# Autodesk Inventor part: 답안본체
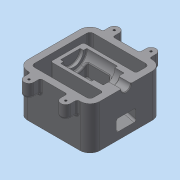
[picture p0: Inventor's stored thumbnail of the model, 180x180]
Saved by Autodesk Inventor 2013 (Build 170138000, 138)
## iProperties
Created: 2018-01
Part Number: 답안본체
Material: 일반
Document SubType Name: Modeling
Designer: dgall
Density: 1 g/cm^3
Author: dgall
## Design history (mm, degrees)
sketch "스케치1"
  geometry: L1 (-55, 55)-(55, 55); L2 (55, 55)-(55, -55); L3 (55, -55)-(-55, -55); L4 (-55, -55)-(-55, 55); 3 further points
  constraints: 8 end point, 2 midpoint, 2 perpendicular, 1 horizontal, 1 horizontal alignment, 1 parallel, 1 vertical alignment
  dimensions: "d0" = 110 distance of L1.start L1.end; "d2" = 110 distance of L1.end L2.end
extrude "돌출1" new body sketch "스케치1" distance "d3" = 65; taper "d4" = 0 deg
fillet "모깎기1" dims "d5" = 15
sketch "스케치2"
  geometry: L1 (55, 65)-(55, 0) reference; L2 (55, 0)-(-55, 0) reference; L3 (-55, 0)-(-55, 65) reference; L4 (-55, 65)-(55, 65) reference; 1 further point
  node "절단 모서리 투영1"
sketch "스케치3"
  geometry: L1 (55, 65)-(55, 0) reference; L2 (55, 0)-(-55, 0) reference; L3 (-55, 0)-(-55, 65) reference; L4 (-55, 65)-(55, 65) reference; L5 (-55, 65)-(55, 65); L6 (-55, 65)-(-55, 57.5); L7 (-55, 57.5)-(-36, 57.5); L8 (-36, 57.5)-(-36, 49); L9 (-36, 49)-(-22, 49); L10 (-22, 49)-(-22, 45); L11 (-22, 45)-(25, 45); L12 (25, 45)-(25, 50); L13 (25, 50)-(30, 50); L14 (30, 50)-(30, 65); 1 further point
  constraints: 20 end point, 5 parallel, 3 perpendicular, 2 point on line, 1 collinear
  dimensions: "d7" = 19 distance of L6.end L7.end; "d9" = 15 diameter of L7 L4; "d10" = 32 diameter of L9 L4; "d11" = 40 diameter of L11 L4; "d13" = 30 diameter of L13 L4; "d14" = 14 distance of L8.end L9.end; "d15" = 47 distance of L10.end L11.end; "d16" = 5 distance of L12.end L13.end
revolve "회전1" sketch "스케치3" stored, may be unused: angle "d17" = 90 deg
sketch "스케치4"
  geometry: L1 (55, 65)-(55, 0) reference; L2 (55, 0)-(-55, 0) reference; L3 (-55, 0)-(-55, 57.5) reference; L4 (-55, 57.5)-(-36, 57.5) reference; L5 (-36, 57.5)-(-36, 49) reference; L6 (-36, 49)-(-22, 49) reference; L7 (-22, 49)-(-22, 45) reference; L8 (-22, 45)-(25, 45) reference; L9 (25, 45)-(25, 50) reference; L10 (25, 50)-(30, 50) reference; L11 (30, 50)-(30, 65) reference; L12 (30, 65)-(55, 65) reference; L13 (-55, 29.061)-(-17, 39.243); L14 (-17, 39.243)-(-17, 45); L15 (-55, 11.061)-(20, 31.157); L16 (20, 31.157)-(20, 45); L17 (-45, 0)-(-45, 8.564); L18 (-45, 8.564)-(35, 30); L19 (35, 30)-(35, 65); L20 (45, 65)-(45, 0); L21 (-17, 45)-(-17, 65); L22 (20, 45)-(20, 65); L23 (20, 65)-(17.646, 65); L24 (17.646, 65)-(-17, 65); 1 further point
  constraints: 24 end point, 8 point on line, 6 parallel, 4 perpendicular, 3 vertical alignment, 1 horizontal alignment
  dimensions: "d19" = 18 distance of L15.start L13.start; "d21" = 37 horizontal distance of L16.end L13.end; "d22" = 75 deg angle of L13 L3; "d23" = 5 distance of L7.end L14.end; "d25" = 30 distance from line of L2 L18.end; "d26" = 10 distance between parallel lines of L20 L19; "d27" = 20 distance between parallel lines of L1 L19; "d28" = 5 distance between parallel lines of L15 L18; "d29" = 10 distance between parallel lines of L3 L17; "d32" = 20 distance of L14.end L21.end; "d34" = 20 distance of L16.end L22.end
  node "절단 모서리 투영3"
extrude "돌출2" cut sketch "스케치4" stored distance "d30" = 90; taper "d31" = 0 deg
extrude "돌출3" join sketch "스케치4" stored distance "d35" = 30; taper "d36" = 0 deg
sketch "스케치5"
  geometry: L1 (-35, 45)-(-35, -45) reference; L2 (55, 7.5)-(55, 40) reference; L3 (40, 55)-(-40, 55) reference; L4 (-40, -55)-(40, -55) reference; L5 (55, -40)-(55, -7.5) reference; L6 (36, 16)-(36, 7.5) reference; L7 (-35, -45)-(45, -45); L8 (45, -45)-(45, -25); L9 (45, -25)-(-35, -25); L10 (-35, 25)-(45, 25); L11 (45, 25)-(45, 45); L12 (45, 45)-(-35, 45); 1 further point
  constraints: 12 end point, 5 perpendicular, 2 point on line, 1 parallel
  dimensions: "d37" = 30 distance between parallel lines of L9 L4; "d39" = 30 distance between parallel lines of L10 L3; "d40" = 10 distance between parallel lines of L8 L5; "d41" = 10 distance between parallel lines of L2 L11
extrude "돌출4" cut sketch "스케치5" stored distance "d42" = 30; taper "d43" = 0 deg
fillet "모깎기2" dims "d44" = 5
fillet "모깎기3" dims "d45" = 3
fillet "모깎기4" dims "d46" = 3
sketch "스케치6"
  geometry: L1 (55, 7.5)-(55, 40) reference; L2 (40, 55)-(-40, 55) reference; L3 (-55, 40)-(-55, -40) reference; L4 (-40, -55)-(40, -55) reference; L5 (36, 16)-(36, 7.5) reference; L6 (35.5, -55)-(35.5, -65); L7 (20.5, -65)-(20.5, -55); L8 (-35.5, -55)-(-35.5, -65); L9 (-20.5, -65)-(-20.5, -55); L10 (20.5, 55)-(20.5, 65); L11 (35.5, 65)-(35.5, 55); L12 (-35.5, 55)-(-35.5, 65); L13 (-20.5, 65)-(-20.5, 55); A1 r 7.5 centre (28, -65) between (20.5, -65) and (35.5, -65); A2 r 7.5 centre (-28, -65) between (-35.5, -65) and (-20.5, -65); A3 r 7.5 centre (28, 65) between (35.5, 65) and (20.5, 65); A4 r 7.5 centre (-28, 65) between (-20.5, 65) and (-35.5, 65); 2 further points
  constraints: 16 end point, 8 point on circle, 8 point on line, 8 tangent, 5 perpendicular, 4 centre point, 3 parallel, 1 equal radius
  dimensions: "d47" = 27 horizontal distance of point (55, -40) A1.centre; "d48" = 7.5 radius of A1; "d49" = 10 distance from line of L4 A1.centre; "d50" = 56 distance of A1.centre A2.centre; "d51" = 27 horizontal distance of L3.end A2.centre; "d52" = 7.5 radius of A2; "d56" = 27 distance from line of A3.centre L1; "d60" = 7.5 radius of A4; "d61" = 56 distance of A3.centre A4.centre; "d62" = 27 distance from line of L3 A4.centre; "d63" = 10 distance from line of L2 A4.centre
extrude "돌출5" join sketch "스케치6" distance "d64" = 20; taper "d65" = 0 deg
hole "구멍1" diameter "d68" = 3.242; stored, may be unused: countersink angle "d72" = 90 deg, drill point angle "d74" = 120 deg; dims "d66" = 10, "d67" = 10, "d69" = 9, "d70" = 4, "d71" = 2, "d73" = 11
hole "구멍2" diameter "d80" = 3.242; stored, may be unused: countersink angle "d84" = 90 deg, drill point angle "d86" = 120 deg; dims "d78" = 10, "d79" = 10, "d81" = 9, "d82" = 4, "d83" = 2, "d85" = 11
fillet "모깎기5" dims "d90" = 1
chamfer "모따기1" distance "d91" = 1; stored, may be unused: second distance "d92" = 2, angle "d93" = 45 deg
fillet "모깎기6" dims "d94" = 3
fillet "모깎기7" dims "d95" = 3
fillet "모깎기8" dims "d96" = 3
extrude "돌출6" cut sketch "스케치4" stored distance "d97" = 30; taper "d98" = 0 deg
fillet "모깎기9" dims "d99" = 3
fillet "모깎기13" dims "d103" = 3
fillet "모깎기14" dims "d104" = 3
fillet "모깎기15" dims "d105" = 3
node "솔리드1"
pattern_linear "직사각형 패턴1" dims "d77" = 56
pattern_linear "직사각형 패턴2" dims "d89" = 56
node "절단 모서리 투영2"
